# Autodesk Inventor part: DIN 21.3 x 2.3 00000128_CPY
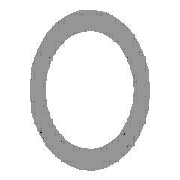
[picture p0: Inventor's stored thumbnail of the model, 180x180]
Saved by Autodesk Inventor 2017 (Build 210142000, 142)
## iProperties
Created: 2017-11
Part Number: DIN 21.3 x 2.3 00000128_CPY
Material: Steel, Mild
Description: Pipe
Document SubType Name: Modeling
Standard: DIN
Designer: iusti
Standard Revision: 2006-07
Standards Organization: DIN
Language: en-US
Size Designation: 21.3 x 2.3
Categories: <MemberInstance><Categories><Category DisplayName="Structural Shapes" InternalName="089c4875-fa83-4c05-b084-43b9cc11f5ed" Mnemonic="GRDR"><CategoryParameter Dis
Stock Number: 21.3 x 2.3
Density: 7.85 g/cm^3
Appearance: Semi-Polished
_CCFamilyMember: 1
_CCFamilyDisplayName: DIN EN 10210-2 - Pipe
_FrameMemberDoc: Frame Member File
_Version: 15.0.0
_GetPNFromCC: 1
IsCustomPart: 1
Author: iusti
G_L: 1000.000 mm
G_W: 21.300 mm
G_H: 21.300 mm
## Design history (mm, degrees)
node "Start plane"
node "End plane"
sketch "Sketch"
  geometry: C1 r 8.35 at (0, 0); C2 r 10.65 at (0, 0); 2 further points
  constraints: 3 coincident, 2 centre point
  dimensions: "d0" = 21.3 diameter of C2 (= G_H); "d1" = 2.3 radial gap between concentric circles of C2 C1 (= G_T)
extrude "Body" new body sketch "Sketch" stored distance "d2" = 1000 (= G_L); taper "d3" = 0 deg
node "Driven Length"
  sketch "Sketch3"
    geometry: L1 (0, 0)-(10, 0) reference
    constraints: 2 end point, 1 horizontal
  workplane "Work Plane3"
  sketch "Sketch4"
    geometry: L1 (-2, 0)-(12, 0) reference; L2 (-2, 1000)-(12, 1000) reference
    dimensions: "d7" = 1000 distance between parallel lines of L1 L2 (derived)
body "Solid1"
other parameters: "G_H" = 21.3 [user parameter; used in 1 equation term], "G_T" = 2.3 [user parameter; used in 1 equation term], "G_L" = 1000 (= d7) [user parameter; used in 1 equation term], "G_OFFSET_START" = 0 [user parameter; used in 1 equation term], "G_OFFSET_END" = 0 [user parameter; used in 1 equation term], "d4" = 0 (computed from G_OFFSET_START), "d6" = 90 deg
